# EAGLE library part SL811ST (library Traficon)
Embedded USB Host/Slave Controller
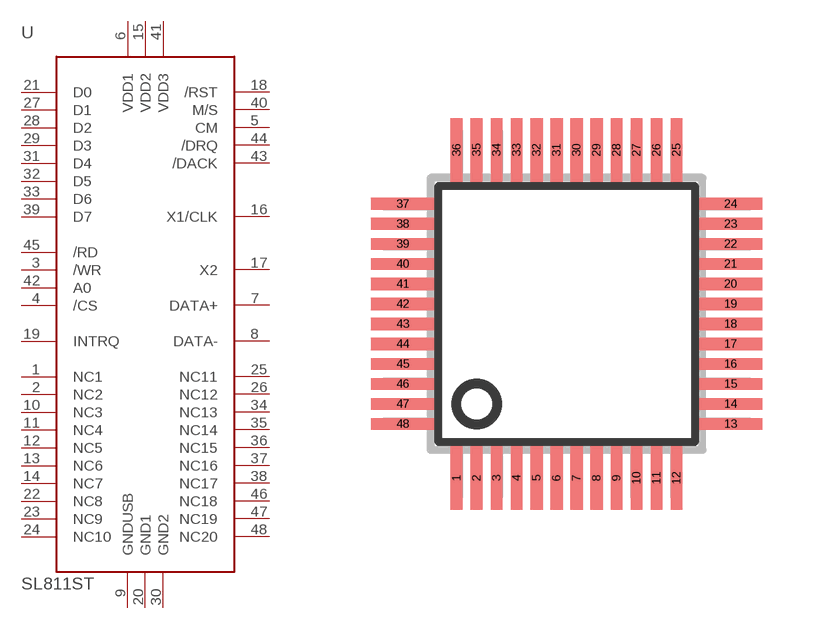
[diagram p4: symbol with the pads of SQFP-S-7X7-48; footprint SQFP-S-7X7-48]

Designator prefix -

## SL811ST  [SQFP-S-7X7-48]
1  NC1  pas
2  NC2  pas
3  /WR  in
4  /CS  in
5  CM  in
6  VDD1  pas
7  DATA+
8  DATA-
9  GNDUSB  pas
10  NC3  pas
11  NC4  pas
12  NC5  pas
13  NC6  pas
14  NC7  pas
15  VDD2  pas
16  X1/CLK  in
17  X2  out
18  /RST  in
19  INTRQ  out
20  GND1  pas
21  D0
22  NC8  pas
23  NC9  pas
24  NC10  pas
25  NC11  pas
26  NC12  pas
27  D1
28  D2
29  D3
30  GND2  pas
31  D4
32  D5
33  D6
34  NC13
35  NC14  pas
36  NC15  pas
37  NC16  pas
38  NC17  pas
39  D7
40  M/S  pas
41  VDD3  pas
42  A0  in
43  /DACK  in
44  /DRQ  out
45  /RD  in
46  NC18  pas
47  NC19  pas
48  NC20  pas

## Footprint SQFP-S-7X7-48 (pad centres in mm)
QFP48 shrink quad flat pack, square
smd 0.3 x 1.6: 1 -2.75,-4.1; 2 -2.25,-4.1; 3 -1.75,-4.1; 4 -1.25,-4.1; 5 -0.75,-4.1; 6 -0.25,-4.1; 7 0.25,-4.1; 8 0.75,-4.1; 9 1.25,-4.1; 10 1.75,-4.1; 11 2.25,-4.1; 12 2.75,-4.1; 25 2.75,4.1; 26 2.25,4.1; 27 1.75,4.1; 28 1.25,4.1; 29 0.75,4.1; 30 0.25,4.1; 31 -0.25,4.1; 32 -0.75,4.1; 33 -1.25,4.1; 34 -1.75,4.1; 35 -2.25,4.1; 36 -2.75,4.1
smd 1.6 x 0.3: 13 4.1,-2.75; 14 4.1,-2.25; 15 4.1,-1.75; 16 4.1,-1.25; 17 4.1,-0.75; 18 4.1,-0.25; 19 4.1,0.25; 20 4.1,0.75; 21 4.1,1.25; 22 4.1,1.75; 23 4.1,2.25; 24 4.1,2.75; 37 -4.1,2.75; 38 -4.1,2.25; 39 -4.1,1.75; 40 -4.1,1.25; 41 -4.1,0.75; 42 -4.1,0.25; 43 -4.1,-0.25; 44 -4.1,-0.75; 45 -4.1,-1.25; 46 -4.1,-1.75; 47 -4.1,-2.25; 48 -4.1,-2.75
